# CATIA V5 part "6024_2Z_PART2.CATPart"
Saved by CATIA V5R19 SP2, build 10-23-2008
Part number: 6024_2Z_PART2
Bounding box of the stored display mesh (mm): x 0 to 28, y -89.975 to 89.975, z -89.975 to 89.975
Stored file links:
  G:\EU_thinkMotion\CFAO_2010\MMS_groupe2\MMS_groupe2\OK\nrosalie\nrosalie_cfao_support_d_arme_legere_final\6024_2Z_PART2.CATPart
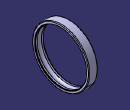
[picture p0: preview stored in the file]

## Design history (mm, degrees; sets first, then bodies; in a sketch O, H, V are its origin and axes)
Set1
  Point1: (0, 0, 0)
  Point2: (1, 0, 0)
  Point3: (0, 1, 0)
  Plane1: type 3Points, Element1 Point1, Element2 Point2, Element3 Point3
Body1 (main body)
  Sketch1 on Plane1, origin (0, 0, 0), H (1, 0, 0), V (0, 1, 0)
    point P1 (0, 88)
    point P2 (0, 82.5)
    line L1 (0, 88) -> (0, 82.5)
    point P3 (0, 82.5)
    point P4 (0.5056, 82.5)
    line L2 (0, 82.5) -> (0.5056, 82.5)
    arc A1 centre (1.1556, 82.5) radius 0.65 from (1.8056, 82.5) to (0.5056, 82.5) ccw
    point P5 (1.8056, 82.5)
    point P6 (2.07, 81)
    line L3 (1.8056, 82.5) -> (2.07, 81)
    point P7 (2.07, 81)
    point P8 (7.121, 81)
    line L4 (2.07, 81) -> (7.121, 81)
    arc A2 centre (14, 75) radius 9.128 from (20.879, 81) to (7.121, 81) ccw
    point P9 (20.879, 81)
    point P10 (25.93, 81)
    line L5 (20.879, 81) -> (25.93, 81)
    point P11 (25.93, 81)
    point P12 (26.1944, 82.5)
    line L6 (25.93, 81) -> (26.1944, 82.5)
    arc A3 centre (26.8444, 82.5) radius 0.65 from (27.4944, 82.5) to (26.1944, 82.5) ccw
    point P13 (27.4944, 82.5)
    point P14 (28, 82.5)
    line L7 (27.4944, 82.5) -> (28, 82.5)
    point P15 (28, 82.5)
    point P16 (28, 88)
    line L8 (28, 82.5) -> (28, 88)
    arc A4 centre (26, 88) radius 2 from (28, 88) to (26, 90) ccw
    point P17 (26, 90)
    point P18 (2, 90)
    line L9 (26, 90) -> (2, 90)
    arc A5 centre (2, 88) radius 2 from (2, 90) to (0, 88) ccw
    point P19 (26, 0)
    point P20 (2, 0)
    axis line L10 (26, 0) -> (2, 0)
    point P21 (0, 88)
    point P22 (0, 82.5)
    point P23 (0, 82.5)
    point P24 (0.5056, 82.5)
    point P25 (1.8056, 82.5)
    point P26 (0.5056, 82.5)
    point P27 (1.8056, 82.5)
    point P28 (2.07, 81)
    point P29 (2.07, 81)
    point P30 (7.121, 81)
    point P31 (20.879, 81)
    point P32 (7.121, 81)
    point P33 (20.879, 81)
    point P34 (25.93, 81)
    point P35 (25.93, 81)
    point P36 (26.1944, 82.5)
    point P37 (27.4944, 82.5)
    point P38 (26.1944, 82.5)
    point P39 (27.4944, 82.5)
    point P40 (28, 82.5)
    point P41 (28, 82.5)
    point P42 (28, 88)
    point P43 (28, 88)
    point P44 (26, 90)
    point P45 (26, 90)
    point P46 (2, 90)
    point P47 (2, 90)
    point P48 (0, 88)
    coincidence: P21 P48, P22 P23, P24 P26, P25 P27, P28 P29, P30 P32, P31 P33, P34 P35, P36 P38, P37 P39, P40 P41, P42 P43, P44 P45, P46 P47
  Shaft1: profile Sketch1, axis Sketch1.L10, angle 360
